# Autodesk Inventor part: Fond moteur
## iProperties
Created: 2002-05
Part Number: Fond moteur
Material: Par défaut
Document SubType Name: Modélisation
Designer: Flavien MARTY
Control State: 0
Master: False
Checked Out: False
Shininess: 20.0
Length Units: 11269
Angle Units: 11279
Time Units: 11290
Mass Units: 11283
Length Display Precision: 3
Angle Display Precision: 2
Compacted: True
Density: 0.0
Volumn: 0.0
Area: 0.0
PropertySet Name: Model Information
Author: Flavien MARTY
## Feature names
1. Extrusion1
2. Congé1 [Fillet]
3. Extrusion2
4. Symétrie1 [Mirror]
5. Extrusion3
6. Congé2 [Fillet]
